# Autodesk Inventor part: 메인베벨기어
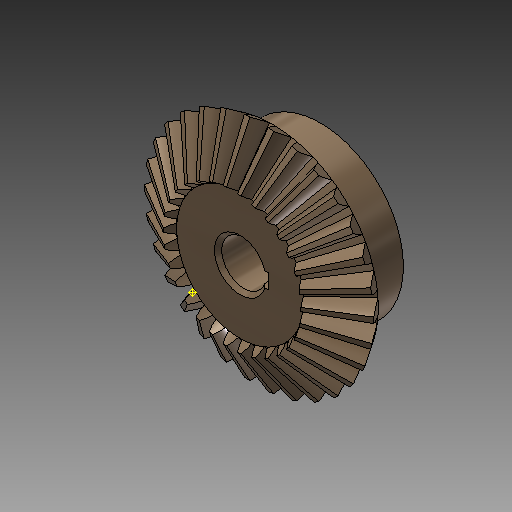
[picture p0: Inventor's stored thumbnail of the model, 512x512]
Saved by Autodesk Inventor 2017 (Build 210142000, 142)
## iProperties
Created: 2018-09
Part Number: 메인베벨기어
Material: 강철, 탄소
Document SubType Name: Modeling
Categories: <?xml version="1.0" encoding="UTF-16"?> <MemberInstance><Categories><FamilyTemplate><FamilyTemplateParameter ValueType="xs:double" Id="1" ObjectReferenceKey="da
Mass: 290.333 g
Surface Area: 107.709 cm^2
Volume: 36.8911 cm^3
Density: 7.87 g/cm^3
Appearance: 얼룩무늬
CustomPartVersion: 1
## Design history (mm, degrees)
node "맨 위 점"
node "메쉬 평면2"
sketch "톱니 본체 스케치"
  geometry: L1 (0, 0)-(28.669, -21.997); L2 (28.669, -21.997)-(31.109, -18.336); L3 (31.109, -18.336)-(0, 0); L4 (30, -20)-(0, 0); L5 (17.219, -13.212)-(18.685, -11.013); L6 (28.669, -21.997)-(17.219, -13.212); L7 (31.109, -18.336)-(18.685, -11.013); L8 (0, -39.387)-(0, 6.564) reference; L9 (0, -20)-(31.109, -20)
  constraints: 16 end point, 4 point on line, 3 perpendicular, 2 collinear, 1 horizontal alignment, 1 vertical alignment
  dimensions: "d0" = 60 diameter of L4.start L8 (= da_de); "d1" = 57.33744 diameter of L1.end L8 (= da_dfe); "d2" = 62.2188 diameter of L2.end L8 (= da_dae); "d3" = 14.4 distance between parallel lines of L2 L5 (= da_b); "d4" = 18.3359 vertical distance of L2.end L1.start (= da_ve)
revolve "톱니 본체" sketch "톱니 본체 스케치" stored, may be unused: angle "d5" = 90 deg
node "시작점"
node "톱니 평면"
sketch "시작 스케치"
  geometry: L1 (0, -23.505)-(0, 10.645) reference; L2 (-0.709, -2.928)-(0.709, -2.928); A1 r 19.188 centre (-19.457, -7.014) between (-0.709, -2.928) and (-3.232, 3.229); A2 r 19.188 centre (19.457, -7.014) between (3.232, 3.229) and (0.709, -2.928); A3 r 57.403 centre (0, -54.083) between (3.232, 3.229) and (-3.232, 3.229); 1 further point
  constraints: 6 point on circle, 3 centre point, 3 symmetric about line, 2 end point, 1 coincident, 1 perpendicular, 1 other
  dimensions: "d7" = 19.18795 radius of A1 (= fd_rr); "d8" = 19.45712 horizontal distance of point (0, -54.083) A1.centre (= fd_x); "d9" = 47.06905 vertical distance of point (0, -54.083) A1.centre (= fd_y); "d57" = 57.40327 radius of A3 (= 0.5 x fd_dva + 0.3 x da_he); "d58" = 51.15527 distance from line of A3.centre L2 (= 0.5 x fd_dva - 1.12 x da_he)
node "끝점"
  node "끝 평면"
sketch "3D 스케치 오른쪽"
  node "Helical Curve Right" dims "d65" = 229.90621 (computed from da_dm, da_delta, da_beta), "d66" = 31.5, "d67" = 60 (= da_de), "d68" = -9.82794 (= -da_delta), "d69" = 8.10972 (computed from fd_loft, da_delta)
node "끝 평면 오른쪽"
sketch "끝 스케치 오른쪽"
  geometry: L1 (0, -41.54)-(0, 13.178) reference; L2 (-0.422, -1.69)-(0.422, -1.69); A1 r 11.427 centre (-11.587, -4.123) between (-0.422, -1.69) and (-1.925, 1.977); A2 r 11.427 centre (11.587, -4.123) between (1.925, 1.977) and (0.422, -1.69); A3 r 34.184 centre (0, -32.153) between (1.925, 1.977) and (-1.925, 1.977); 1 further point
  constraints: 6 point on circle, 3 centre point, 3 symmetric about line, 2 end point, 1 coincident, 1 perpendicular, 1 other
  dimensions: "d70" = 11.58699 horizontal distance of A3.centre A1.centre (computed from fd_x, fd_ratio); "d71" = 28.03028 vertical distance of point (0, -32.153) A1.centre (computed from fd_y, fd_ratio); "d72" = 11.4267 radius of A1 (computed from fd_rr, fd_ratio); "d73" = 30.46369 distance from line of point (0, -32.153) L2 (computed from d58, fd_ratio); "d74" = 34.18446 radius of A3 (computed from d57, fd_ratio)
feature "로프트 오른쪽" sketch "끝 스케치 오른쪽" dims "d75" = 0, "d77" = 0, "d79" = 0, "d80" = 90 deg, "d85" = 20, "d92" = 90 deg, "d93" = 90 deg, "da_teethtype" = 0 [user parameter]
sketch "3D 스케치 왼쪽"
  node "Helical Curve Left" dims "d26" = 229.90621 (computed from da_dm, da_delta, da_beta), "d27" = 8.10972 (computed from fd_loft, da_delta), "d28" = 60 (= da_de), "d29" = -9.82794 (= -da_delta)
node "끝 평면 왼쪽"
sketch "끝 스케치 왼쪽" dims "d56" = 10.3728 (derived)
  geometry: L1 (0, -43.753)-(0, 15.405) reference; L2 (-0.422, -1.678)-(0.422, -1.678); A1 r 11.427 centre (-11.587, -4.111) between (-0.422, -1.678) and (-1.925, 1.988); A2 r 11.427 centre (11.587, -4.111) between (1.925, 1.988) and (0.422, -1.678); A3 r 34.184 centre (0, -32.142) between (1.925, 1.988) and (-1.925, 1.988); 2 further points; 1 other entity
  constraints: 6 point on circle, 3 centre point, 3 symmetric about line, 2 end point, 1 coincident, 2 other
  dimensions: "d30" = 11.4267 radius of A1 (computed from fd_rr, fd_ratio); "d31" = 11.58699 horizontal distance of point (0, -32.142) A1.centre (computed from fd_x, fd_ratio); "d32" = 28.03028 vertical distance of A1.centre point (0, -32.142) (computed from fd_y, fd_ratio); "d61" = 34.18446 radius of A3 (computed from d57, fd_ratio); "d62" = 30.46369 distance from line of point (0, -32.142) L2 (computed from d58, fd_ratio)
feature "로프트 왼쪽" sketch "끝 스케치 왼쪽" dims "d35" = 0, "d37" = 0, "d39" = 0, "d40" = 90 deg, "d84" = 10, "d90" = 90 deg, "d91" = 90 deg, "da_teethtype" = 0 [user parameter]
sketch "본체 스케치"
  geometry: L1 (0, -35.038)-(0, -19.531) reference; L2 (28.669, -21.997)-(17.219, -13.212) reference; L3 (17.219, -13.212)-(0, -13.212); L4 (28.669, -21.997)-(0, -21.997)
  constraints: 4 end point, 2 perpendicular, 2 point on line
revolve "본체 고정" sketch "본체 스케치" stored, may be unused: angle "d46" = 90 deg
feature "피치 지름" dims angle "d47" = 90 deg
sketch "스케치8"
  geometry: C1 r 22.5 at (0, 0); 1 further point
  constraints: 1 centre point, 1 coincident
  dimensions: "d94" = 45 diameter of C1
extrude "돌출1" join sketch "스케치8" distance "d95" = 13; taper "d96" = 0 deg
sketch "스케치9"
  geometry: 1 further point
hole "구멍1" sketch "스케치9" at (0, 0) diameter "d97" = 12; stored, may be unused: countersink angle "d101" = 90 deg, drill point angle "d103" = 118 deg; dims "d98" = 6, "d99" = 4, "d100" = 2, "d102" = 8
sketch "스케치10"
  geometry: L1 (5.657, 2)-(7.8, 2); L2 (7.8, 2)-(7.8, -2); L3 (7.8, -2)-(5.657, -2); A1 r 6 centre (0, 0) between (5.657, 2) and (5.657, -2) reference; 1 further point
  constraints: 6 end point, 2 parallel, 2 point on circle, 1 horizontal, 1 perpendicular
  dimensions: "d104" = 4 distance of L1.end L2.end; "d112" = 13.8 dimension on A1 L2
extrude "돌출2" cut sketch "스케치10" stored distance "d106" = 10; taper "d107" = 0 deg
chamfer "모따기1" distance "d108" = 1; stored, may be unused: second distance "d109" = 2, angle "d110" = 45 deg
fillet "모깎기1" dims "d111" = 2
body "Solid1"
feature "로프트" dims "d17" = 0, "d18" = 90 deg, "d19" = 0, "d20" = 90 deg, "d89" = 0, "da_teethtype" = 0 [user parameter]
pattern_circular "원형 패턴" dims angle "d22" = 360 deg, "d88" = 0, "da_teethtype" = 0 [user parameter]
pattern_circular "원형 패턴 오른쪽" dims angle "d82" = 360 deg, "da_teethtype" = 0 [user parameter]
pattern_circular "원형 패턴 왼쪽" dims angle "d42" = 360 deg, "da_teethtype" = 0 [user parameter]
sketch "끝 스케치"
  geometry: L1 (0, -15.359)-(0, 6.983) reference; L2 (-0.422, -1.69)-(0.422, -1.69); A1 r 11.427 centre (-11.587, -4.123) between (-0.422, -1.69) and (-1.925, 1.977); A2 r 11.427 centre (11.587, -4.123) between (1.925, 1.977) and (0.422, -1.69); A3 r 34.184 centre (0, -32.153) between (1.925, 1.977) and (-1.925, 1.977); 1 further point
  constraints: 6 point on circle, 3 centre point, 3 symmetric about line, 2 end point, 1 coincident, 1 other
  dimensions: "d12" = 11.4267 radius of A1 (computed from fd_rr, fd_ratio); "d15" = 11.58699 horizontal distance of A1.centre point (0, -32.153) (computed from fd_x, fd_ratio); "d16" = 28.03028 vertical distance of A1.centre point (0, -32.153) (computed from fd_y, fd_ratio); "d59" = 34.18446 radius of A3 (computed from d57, fd_ratio); "d60" = 30.46369 distance from line of A3.centre L2 (computed from d58, fd_ratio)
sketch "Sketch6"
  geometry: L1 (30, -20)-(0, 0) reference; L2 (0, -37.8)-(0, 6.3) reference
body "Srf1"
other parameters: "da_b" = 14.4 [user parameter; used in 2 equation terms], "da_de" = 60 [user parameter; used in 4 equation terms], "da_dae" = 62.2188 [user parameter; used in 2 equation terms], "da_dfe" = 57.33744 [user parameter; used in 1 equation term], "da_le" = 36.05551 [user parameter; used in 1 equation term], "da_omega" = 90 deg [user parameter; used in 1 equation term], "da_beta" = 0 [user parameter; used in 2 equation terms], "da_delta" = 9.82794 [user parameter; used in 8 equation terms], "da_alpha" = 20 deg [user parameter; used in 2 equation terms], "da_he" = 4.4 [user parameter; used in 4 equation terms], "da_ve" = 18.3359 [user parameter; used in 1 equation term], "fd_dv" = 108.16654 (computed from da_de, da_delta) [user parameter; used in 1 equation term], "fd_dva" = 112.16654 (computed from da_dae, da_delta) [user parameter; used in 3 equation terms], "fd_dvb" = 101.6433 (computed from fd_dv, da_alpha) [user parameter; used in 2 equation terms], "da_zv" = 540.83269 [user parameter; used in 1 equation term], "fd_loft" = 14.62 (= da_b + 0.05 x da_he) [user parameter; used in 4 equation terms], "fd_ratio" = 5.95514 (computed from da_le, fd_loft) [user parameter; used in 15 equation terms], "fd_rr" = 19.18795 (computed from fd_dd, fd_dvb) [user parameter; used in 6 equation terms], "fd_angle" = 0.29367 (computed from da_zv) [user parameter; used in 4 equation terms], "fd_x1" = 1.58802 (computed from da_dvw, fd_angle) [user parameter; used in 1 equation term], "fd_y1" = 54.05995 (computed from da_dvw, fd_angle) [user parameter; used in 1 equation term], "fd_x2" = 17.8691 (computed from fd_rr, fd_angle2, fd_angle) [user parameter; used in 1 equation term], "fd_y2" = 6.9909 (computed from fd_rr, fd_angle2, fd_angle) [user parameter; used in 1 equation term], "fd_x" = 19.45712 (= fd_x1 + fd_x2) [user parameter; used in 4 equation terms], "fd_y" = 47.06905 (= fd_y1 - fd_y2) [user parameter; used in 4 equation terms], "fd_angle2" = 3.43555 (computed from fd_dvb, fd_dd, da_alpha) [user parameter; used in 2 equation terms], "fd_dd" = 108.64654 (= fd_dva - 0.8 x da_he) [user parameter; used in 2 equation terms], "da_dvw" = 108.16654 [user parameter; used in 2 equation terms], "d11" = 14.62 (= fd_loft), "da_dm" = 48.01848 [user parameter; used in 2 equation terms], "da_x" = 0 [user parameter], "da_m" = 2 [user parameter], "d48" = 0, "d49" = 0, "d50" = 90 deg (= da_omega), "d51" = 6 deg (computed from da_z), "d52" = 0, "d53" = 0, "d54" = 0
